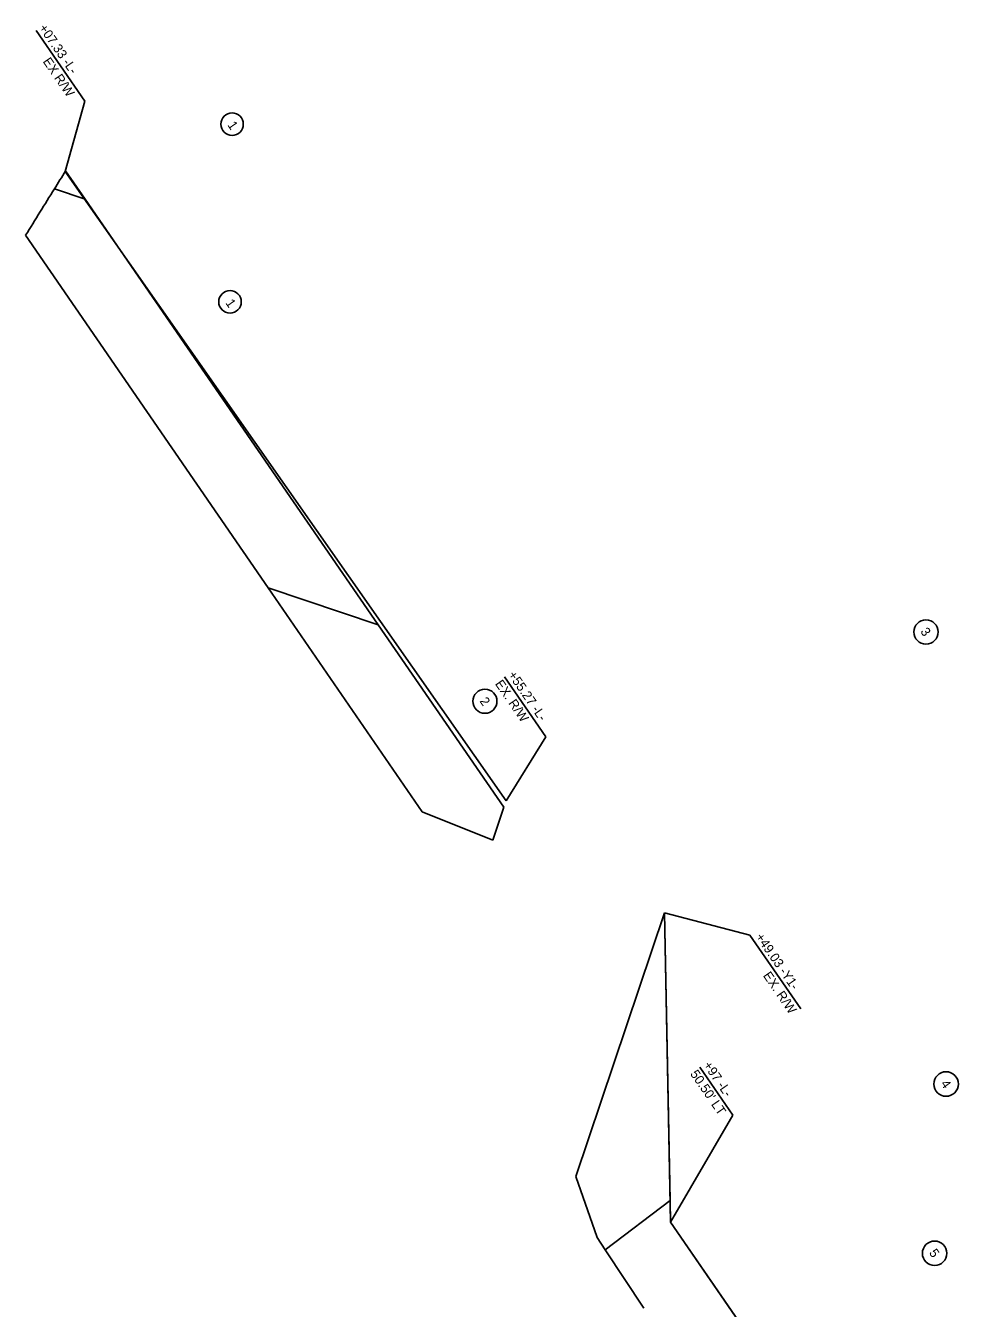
# Model space of a CAD drawing. Extents: x 2298011 to 2299093, y 599361 to 600353.
# Drawn here: x 2298111.5 to 2298412.4, y 599939.6 to 600353.5 of the extents above; entities that cross this region are included whole.
import ezdxf

# ---------------------------------------------------------------- set-up
doc = ezdxf.new("R2010")
doc.units = 0
for name, color, linetype in [('Prop Easement Construction', 7, 'Continuous'), ('Prop Easement Construction Station Offsets', 7, 'Continuous'), ('Prop Parcel Number Text', 7, 'Continuous'), ('Scratch_Level_6', 7, 'Continuous')]:
    doc.layers.add(name, color=color, linetype=linetype)

msp = doc.modelspace()

# ---------------------------------------------------------------- linework, layer by layer
at = {"layer": 'Prop Easement Construction'}
for p, q in [((2298124.25, 600306.42), (2298266.48, 600103.32)), ((2298317.62, 600067.17), (2298319.51, 599967.44)), ((2298319.51, 599967.44), (2298365.22, 599901.13))]:
    msp.add_line(p, q, dxfattribs=at)
at = {"layer": 'Prop Easement Construction Station Offsets'}
for p, q in [((2298130.58, 600329.13), (2298114.86, 600351.96)), ((2298279.25, 600124.02), (2298265.96, 600143.31)), ((2298361.55, 600036.21), (2298345.17, 600060)), ((2298339.69, 600001.89), (2298328.97, 600017.45))]:
    msp.add_line(p, q, dxfattribs=at)
for points in [[(2298130.58, 600329.13), (2298124.25, 600306.42)], [(2298279.25, 600124.02), (2298266.48, 600103.32)], [(2298345.17, 600060), (2298317.62, 600067.17)], [(2298339.69, 600001.89), (2298319.51, 599967.44)]]:
    msp.add_lwpolyline(points, dxfattribs=at)
at = {"layer": 'Prop Parcel Number Text'}
for centre, radius in [((2298178.06, 600321.72), 3.63), ((2298177.4, 600264.34), 3.63), ((2298401.95, 600157.83), 3.92), ((2298259.65, 600135.49), 3.89), ((2298408.45, 600011.97), 3.96), ((2298404.74, 599957.35), 3.94)]:
    msp.add_circle(centre, radius, dxfattribs=at)
at = {"layer": 'Scratch_Level_6'}
for p, q in [((2298130.66, 600297.45), (2298124.36, 600306.6)), ((2298120.73, 600300.79), (2298130.66, 600297.45)), ((2298130.66, 600297.45), (2298120.73, 600300.79)), ((2298225.21, 600160.18), (2298130.66, 600297.45)), ((2298111.46, 600285.84), (2298189.67, 600172.13)), ((2298189.67, 600172.13), (2298225.21, 600160.18)), ((2298189.67, 600172.13), (2298239.4, 600099.82)), ((2298225.21, 600160.18), (2298189.67, 600172.13)), ((2298265.79, 600101.28), (2298225.21, 600160.18)), ((2298262.2, 600090.61), (2298265.79, 600101.28)), ((2298239.4, 600099.82), (2298262.2, 600090.61)), ((2298317.62, 600067.17), (2298289.03, 599982.08)), ((2298319.38, 599974.42), (2298317.62, 600067.17)), ((2298289.03, 599982.08), (2298295.84, 599962.45)), ((2298298.48, 599958.44), (2298319.38, 599974.42)), ((2298319.38, 599974.42), (2298298.48, 599958.44)), ((2298319.51, 599967.44), (2298319.38, 599974.42)), ((2298343.6, 599932.49), (2298319.51, 599967.44)), ((2298295.84, 599962.45), (2298298.48, 599958.44)), ((2298298.48, 599958.44), (2298310.89, 599939.59))]:
    msp.add_line(p, q, dxfattribs=at)
for start, end in [(147.89006, 148.03026), (148.03026, 148.39034)]:
    msp.add_arc((2300495.07, 598818.88), 2798.85, start, end, dxfattribs=at)

# ---------------------------------------------------------------- texts
at = {"layer": 'Prop Easement Construction Station Offsets'}
for s, p in [('+07.33 -L-', (2298115.59, 600352.73)), ('EX R/W', (2298116.87, 600341.92)), ('EX. R/W', (2298262.78, 600141.1)), ('+55.27 -L-', (2298266.97, 600143.98)), ('+49.03 -Y1-', (2298346.83, 600059.42)), ('EX. R/W', (2298349.25, 600046.96)), ('+97 -L-', (2298329.98, 600018.06)), ("50.50' LT", (2298325.75, 600015.24))]:
    msp.add_text(s, height=3, rotation=304.5541, dxfattribs=at).set_placement(p)
at = {"layer": 'Prop Parcel Number Text'}
for s, rotation, p in [('1', 304.5541, (2298176.46, 600321.4)), ('1', 304.5541, (2298175.8, 600264.02)), ('3', 305.4767, (2298400.02, 600157.94)), ('2', 305.4767, (2298257.81, 600135.49)), ('4', 305.4767, (2298406.57, 600012.02)), ('5', 305.4767, (2298402.82, 599957.46))]:
    msp.add_text(s, height=3, rotation=rotation, dxfattribs=at).set_placement(p)

doc.saveas('drawing.dxf')
